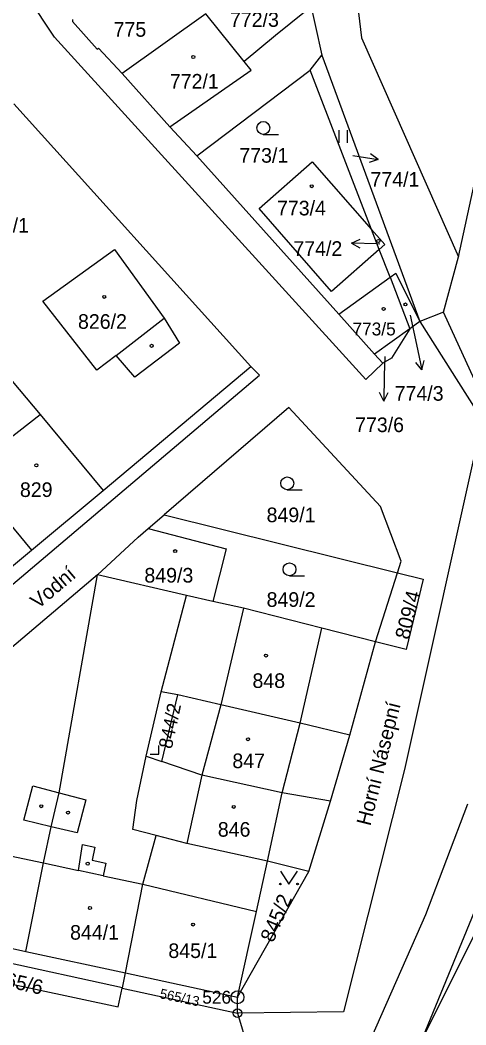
# Model space of a CAD drawing. Extents: x -776701 to -776081, y -974398 to -973771.
# Drawn here: x -776240.6 to -776188.7, y -974065.8 to -973949 of the extents above; entities that cross this region are included whole.
import ezdxf

# ---------------------------------------------------------------- set-up
doc = ezdxf.new("R2010")
doc.units = 0
for name, color, linetype in [('Hranice parcel', 7, 'Continuous'), ('Parcelní čísla', 7, 'Continuous'), ('Pop  PČ popisy', 7, 'Continuous'), ('Poz předměty', 7, 'Continuous'), ('Vnitřní kresba', 7, 'Continuous'), ('Značky bodu BP', 7, 'Continuous'), ('Značky budov', 7, 'Continuous'), ('Značky kultur', 7, 'Continuous')]:
    doc.layers.add(name, color=color, linetype=linetype)

msp = doc.modelspace()

# ---------------------------------------------------------------- linework, layer by layer
at = {"layer": 'Hranice parcel'}
for p, q in [((-776189.59, -973976.54), (-776179.58, -973929.94)), ((-776208.49, -973939.59), (-776205.5, -973953.09)), ((-776219, -973948.3), (-776228.72, -973955.21)), ((-776231.48, -973952.27), (-776228.72, -973955.21)), ((-776206.87, -973954.83), (-776205.5, -973953.09)), ((-776205.5, -973953.09), (-776194.09, -973984.05)), ((-776220.04, -973964.78), (-776206.87, -973954.83)), ((-776199.71, -973973.36), (-776206.87, -973954.83)), ((-776203.53, -973983.2), (-776220.04, -973964.78)), ((-776198.82, -973975.67), (-776199.71, -973973.36)), ((-776197.57, -973978.91), (-776198.82, -973975.67)), ((-776203.53, -973983.2), (-776197.57, -973978.91)), ((-776197.57, -973978.91), (-776195.26, -973984.89)), ((-776199.38, -973987.83), (-776203.53, -973983.2)), ((-776194.09, -973984.05), (-776195.26, -973984.89)), ((-776194.09, -973984.05), (-776186.87, -973995.48)), ((-776195.26, -973984.89), (-776199.38, -973987.83)), ((-776239.27, -974010.62), (-776230.92, -974003.68)), ((-776225.69, -974008.12), (-776223.84, -974006.53)), ((-776223.84, -974006.53), (-776196.71, -974013.25)), ((-776247.57, -974017.58), (-776239.27, -974010.62)), ((-776231.58, -974013.49), (-776242.81, -974023.05)), ((-776221.22, -974015.91), (-776231.58, -974013.49)), ((-776199.27, -974021.29), (-776196.71, -974013.25)), ((-776224.19, -974027.09), (-776221.22, -974015.91)), ((-776218.16, -974016.6), (-776221.22, -974015.91)), ((-776202.25, -974032.14), (-776199.27, -974021.29)), ((-776172.13, -974024.06), (-776193.76, -974067.27)), ((-776225.94, -974034.56), (-776224.19, -974027.09)), ((-776222.25, -974027.45), (-776224.19, -974027.09)), ((-776224.09, -974035.2), (-776222.25, -974027.45)), ((-776204.48, -974039.81), (-776202.25, -974032.14)), ((-776225.94, -974034.56), (-776224.09, -974035.2)), ((-776207.02, -974047.99), (-776204.48, -974039.81)), ((-776207.02, -974047.99), (-776211.83, -974046.79)), ((-776215.3, -974062.6), (-776207.02, -974047.99)), ((-776252.12, -974054.65), (-776239.9, -974057.27)), ((-776239.9, -974057.27), (-776228.31, -974059.76)), ((-776228.69, -974061.51), (-776228.31, -974059.76)), ((-776228.31, -974059.76), (-776215.3, -974062.6)), ((-776228.71, -974061.56), (-776228.69, -974061.51)), ((-776228.71, -974061.56), (-776215.3, -974064.46)), ((-776215.3, -974064.46), (-776215.3, -974062.6)), ((-776215.3, -974064.46), (-776212.94, -974072.41))]:
    msp.add_line(p, q, dxfattribs=at)
for points in [[(-776213.8, -973922.1), (-776202.27, -973939.42), (-776200.89, -973951.06), (-776189.59, -973976.54)], [(-776210.07, -973940.9), (-776207.31, -973947.95), (-776210.89, -973950.8), (-776214.54, -973953.81), (-776219, -973948.3)], [(-776234.47, -973948.93), (-776234.5, -973949.16), (-776231.62, -973952.39), (-776231.48, -973952.27)], [(-776228.72, -973955.21), (-776223.16, -973961.44), (-776220.04, -973964.78)], [(-776230.92, -974003.68), (-776213.75, -973989.29), (-776241.31, -973958.73)], [(-776198.82, -973975.67), (-776204.36, -973980.57), (-776212.78, -973970.92), (-776206.63, -973965.5), (-776199.71, -973973.36)], [(-776199.71, -973973.36), (-776198.18, -973975.1), (-776198.82, -973975.67)], [(-776229.6, -973975.7), (-776223.82, -973983.68), (-776222.05, -973986.58), (-776227.23, -973990.52), (-776229.42, -973987.99), (-776231.67, -973989.69), (-776237.93, -973981.67), (-776229.6, -973975.7)], [(-776186.46, -973993.62), (-776191.35, -973982.98), (-776189.59, -973976.54)], [(-776197.57, -973978.91), (-776196.89, -973978.42), (-776194.09, -973984.05)], [(-776195.26, -973984.89), (-776197.38, -973988.31), (-776198.41, -973988.91), (-776199.38, -973987.83)], [(-776243.98, -973988.1), (-776238.25, -973994.88), (-776230.92, -974003.68)], [(-776196.71, -974013.25), (-776196.28, -974011.91), (-776198.67, -974005.55), (-776209.34, -973994.03), (-776223.84, -974006.53)], [(-776253.07, -973994.57), (-776247.18, -974001.31), (-776246.82, -974001.54), (-776239.27, -974010.62)], [(-776186.87, -973995.48), (-776195.9, -974036.12), (-776202.98, -974064.31), (-776215.3, -974064.46)], [(-776231.58, -974013.49), (-776226.86, -974009.13), (-776225.69, -974008.12)], [(-776225.69, -974008.12), (-776216.63, -974010.46), (-776218.16, -974016.6)], [(-776239.9, -974057.27), (-776237.86, -974046.99), (-776236.96, -974042.81), (-776236.02, -974038.84), (-776231.58, -974013.49)], [(-776196.71, -974013.25), (-776193.7, -974014), (-776195.7, -974022.19), (-776199.27, -974021.29)], [(-776199.27, -974021.29), (-776205.48, -974019.71), (-776214.61, -974017.38), (-776218.16, -974016.6)], [(-776193.76, -974067.27), (-776174.47, -974020.28), (-776171.99, -974017.55)], [(-776202.25, -974032.14), (-776208.03, -974030.74), (-776217.23, -974028.62), (-776222.25, -974027.45)], [(-776224.75, -974043.8), (-776227.47, -974043.1), (-776227, -974039.72), (-776225.94, -974034.56)], [(-776204.48, -974039.81), (-776210.09, -974038.84), (-776219.45, -974036.78), (-776224.09, -974035.2)], [(-776228.31, -974059.76), (-776226.31, -974049.45), (-776224.75, -974043.8)], [(-776211.83, -974046.79), (-776221.19, -974044.73), (-776224.75, -974043.8)], [(-776215.3, -974062.6), (-776213.1, -974052.64), (-776211.83, -974046.79)], [(-776252.47, -974056.28), (-776252.98, -974058.63), (-776229.18, -974063.72), (-776228.71, -974061.56)]]:
    msp.add_lwpolyline(points, dxfattribs=at)
at = {"layer": 'Pop  PČ popisy'}
for p, q in [((-776201.9, -973964.75), (-776198.94, -973965.22)), ((-776198.94, -973965.22), (-776199.85, -973964.57)), ((-776198.94, -973965.22), (-776200, -973965.56)), ((-776202.06, -973974.94), (-776201.04, -973974.47)), ((-776199.06, -973975.04), (-776202.06, -973974.94)), ((-776202.06, -973974.94), (-776201.08, -973975.47)), ((-776198.77, -973975.06), (-776199.06, -973975.04)), ((-776195.21, -973983.31), (-776194.49, -973986.74)), ((-776194.49, -973986.74), (-776193.87, -973989.68)), ((-776198.18, -973988.13), (-776198.24, -973990.31)), ((-776193.87, -973989.68), (-776194.56, -973988.8)), ((-776193.87, -973989.68), (-776193.58, -973988.59)), ((-776198.24, -973990.31), (-776198.29, -973993.31)), ((-776198.29, -973993.31), (-776198.78, -973992.3)), ((-776198.29, -973993.31), (-776197.77, -973992.32))]:
    msp.add_line(p, q, dxfattribs=at)
at = {"layer": 'Poz předměty'}
for p, q in [((-776188.57, -974040.14), (-776193.46, -974053.03)), ((-776193.46, -974053.03), (-776205.51, -974080.41))]:
    msp.add_line(p, q, dxfattribs=at)
at = {"layer": 'Vnitřní kresba'}
for p, q in [((-776236.59, -973950.99), (-776296.16, -973861.12)), ((-776200.39, -973990.8), (-776236.59, -973950.99)), ((-776213.7, -973954.84), (-776214.54, -973953.81)), ((-776223.16, -973961.44), (-776213.7, -973954.84)), ((-776191.35, -973982.98), (-776194.09, -973984.05)), ((-776229.42, -973987.99), (-776223.82, -973983.68)), ((-776212.73, -973990.29), (-776213.75, -973989.29)), ((-776198.41, -973988.91), (-776200.39, -973990.8)), ((-776246.47, -974018.84), (-776212.73, -973990.29)), ((-776246.82, -974001.54), (-776238.25, -973994.88)), ((-776214.61, -974017.38), (-776217.23, -974028.62)), ((-776208.03, -974030.74), (-776205.48, -974019.71)), ((-776217.23, -974028.62), (-776219.45, -974036.78)), ((-776210.09, -974038.84), (-776208.03, -974030.74)), ((-776219.45, -974036.78), (-776221.19, -974044.73)), ((-776240.13, -974042), (-776239.09, -974038.04)), ((-776239.09, -974038.04), (-776236.02, -974038.84)), ((-776236.02, -974038.84), (-776232.95, -974039.65)), ((-776232.95, -974039.65), (-776233.93, -974043.5)), ((-776211.83, -974046.79), (-776210.09, -974038.84)), ((-776236.96, -974042.81), (-776240.13, -974042)), ((-776233.93, -974043.5), (-776236.96, -974042.81)), ((-776233.79, -974047.85), (-776233.31, -974044.85)), ((-776233.31, -974044.85), (-776231.9, -974045.15)), ((-776231.9, -974045.15), (-776232.22, -974046.68)), ((-776241.74, -974046.16), (-776237.86, -974046.99)), ((-776232.22, -974046.68), (-776230.62, -974047.03)), ((-776237.86, -974046.99), (-776233.79, -974047.85)), ((-776230.92, -974048.47), (-776233.79, -974047.85)), ((-776230.62, -974047.03), (-776230.92, -974048.47)), ((-776230.92, -974048.47), (-776226.31, -974049.45)), ((-776226.31, -974049.45), (-776213.1, -974052.64)), ((-776228.69, -974061.51), (-776252.47, -974056.28))]:
    msp.add_line(p, q, dxfattribs=at)
at = {"layer": 'Značky bodu BP'}
for centre, radius in [((-776215.3, -974062.6), 0.75), ((-776215.3, -974062.6), 0.03), ((-776215.3, -974064.46), 0.5), ((-776215.3, -974064.46), 0.0303)]:
    msp.add_circle(centre, radius, dxfattribs=at)
at = {"layer": 'Značky budov'}
for centre in [(-776220.44, -973953.3), (-776206.67, -973968.33), (-776198.92, -973974.7), (-776230.8, -973981.19), (-776198.31, -973982.59), (-776195.77, -973982.07), (-776225.29, -973986.88), (-776238.69, -974000.77), (-776222.55, -974010.74), (-776211.99, -974022.88), (-776214.08, -974032.61), (-776238.13, -974040.4), (-776215.74, -974040.47), (-776235.01, -974041.13), (-776232.72, -974047.07), (-776232.46, -974052.23), (-776220.46, -974054.15)]:
    msp.add_circle(centre, 0.175, dxfattribs=at)
at = {"layer": 'Značky kultur'}
for p, q in [((-776212.3, -973962.3), (-776210.55, -973962.3)), ((-776203.5, -973963.3), (-776203.5, -973961.8)), ((-776202.5, -973963.3), (-776202.5, -973961.8)), ((-776209.52, -974003.61), (-776207.77, -974003.61)), ((-776209.26, -974013.61), (-776207.51, -974013.61)), ((-776224.44, -974034.34), (-776224.44, -974033.34)), ((-776225.44, -974034.34), (-776224.44, -974034.34))]:
    msp.add_line(p, q, dxfattribs=at)
msp.add_lwpolyline([(-776210.32, -974047.94), (-776209.32, -974049.44), (-776208.32, -974047.94)], dxfattribs=at)
for centre, radius in [((-776212.3, -973961.55), 0.75), ((-776209.52, -974002.86), 0.75), ((-776209.26, -974012.86), 0.75), ((-776210.32, -974049.44), 0.1), ((-776208.32, -974049.44), 0.1)]:
    msp.add_circle(centre, radius, dxfattribs=at)

# ---------------------------------------------------------------- texts
at = {"layer": 'Parcelní čísla'}
for s, height, p in [('772/3', 1.7, (-776216.18, -973949.8)), ('775', 1.7, (-776229.71, -973950.95)), ('772/1', 1.7, (-776223.17, -973956.98)), ('773/1', 1.7, (-776215.09, -973965.59)), ('774/1', 1.7, (-776199.84, -973968.38)), ('773/4', 1.7, (-776210.71, -973971.72)), ('826/1', 1.7, (-776245.24, -973973.72)), ('774/2', 1.7, (-776208.81, -973976.42)), ('826/2', 1.7, (-776233.85, -973984.9)), ('773/5', 1.5, (-776201.93, -973985.67)), ('774/3', 1.7, (-776197.03, -973993.26)), ('773/6', 1.7, (-776201.63, -973996.91)), ('829', 1.7, (-776240.6, -974004.45)), ('849/1', 1.7, (-776211.92, -974007.38)), ('849/3', 1.7, (-776226.13, -974014.4)), ('849/2', 1.7, (-776211.92, -974017.22)), ('848', 1.7, (-776213.56, -974026.65)), ('847', 1.7, (-776215.9, -974035.97)), ('846', 1.7, (-776217.59, -974043.94)), ('844/1', 1.7, (-776234.77, -974055.91)), ('845/1', 1.7, (-776223.34, -974058.04))]:
    msp.add_text(s, height=height, dxfattribs=at).set_placement(p)
for s, height, rotation, p in [('809/4', 1.7, 76, (-776195.36, -974021.11)), ('844/2', 1.584, 78, (-776222.95, -974033.81)), ('845/2', 1.7, 67, (-776211.15, -974056.33)), ('565/6', 1.7, 347, (-776243.68, -974061.05)), ('565/13', 1.139, 348, (-776224.42, -974062.7))]:
    msp.add_text(s, height=height, rotation=rotation, dxfattribs=at).set_placement(p)
at = {"layer": 'Pop  PČ popisy'}
for s, rotation, p in [('Vodní', 40, (-776238.5, -974017.53)), ('Horní Násepní', 76, (-776199.85, -974042.76))]:
    msp.add_text(s, height=1.7, rotation=rotation, dxfattribs=at).set_placement(p)
at = {"layer": 'Značky bodu BP'}
msp.add_text('526', height=1.5, dxfattribs=at).set_placement((-776219.4, -974063.35))

doc.saveas('drawing.dxf')
